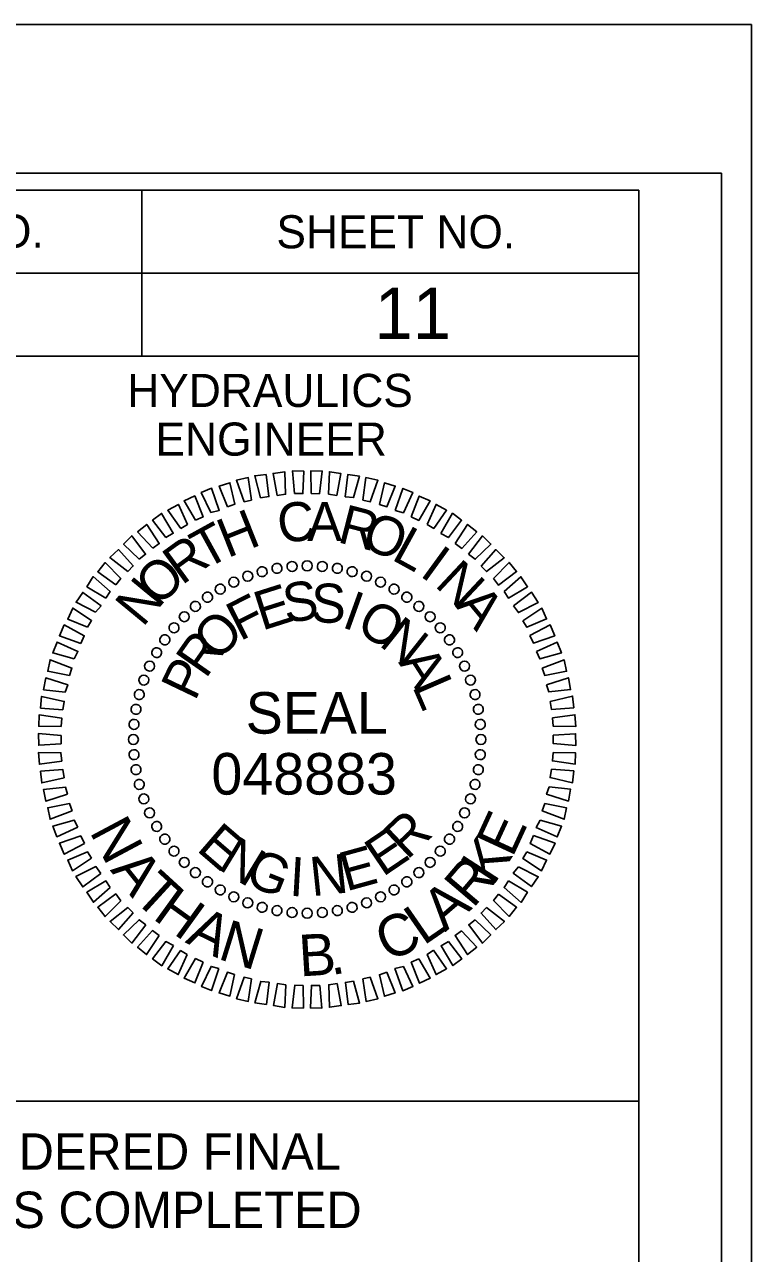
# Model space of a CAD drawing. Extents: x 1648157 to 1650776, y 832691 to 834781.
# Drawn here: x 1650436.6 to 1650546.3, y 833605.5 to 833791 of the extents above; entities that cross this region are included whole.
import ezdxf

# ---------------------------------------------------------------- set-up
doc = ezdxf.new("R2010")
doc.units = 0
for name, color, linetype in [('Default', 7, 'Continuous'), ('Old_Level_2', 7, 'Continuous'), ('Sheet Cutting Line CELL', 7, 'Continuous'), ('Sheet Data Field CELL', 7, 'Continuous'), ('Sheet Plot Border Inside CELL', 7, 'Continuous'), ('Sheet Plot Border Outside CELL', 7, 'Continuous'), ('Sheet Profile CELL', 7, 'Continuous'), ('Sheet Sticker Exception Certification CELL', 7, 'Continuous')]:
    doc.layers.add(name, color=color, linetype=linetype)

msp = doc.modelspace()

# ---------------------------------------------------------------- linework, layer by layer
at = {"layer": 'Old_Level_2'}
for p, q in [((1650474.7, 833708.89), (1650474.7, 833708.89)), ((1650476.94, 833709.25), (1650476.94, 833709.25)), ((1650479.24, 833709.34), (1650479.24, 833709.34)), ((1650481.55, 833709.22), (1650481.55, 833709.22)), ((1650483.8, 833708.9), (1650483.8, 833708.9)), ((1650468.15, 833706.9), (1650468.15, 833706.9)), ((1650470.22, 833707.77), (1650470.22, 833707.77)), ((1650472.41, 833708.44), (1650472.41, 833708.44)), ((1650486.01, 833708.46), (1650486.01, 833708.46)), ((1650488.21, 833707.77), (1650488.21, 833707.77)), ((1650490.32, 833706.87), (1650490.32, 833706.87)), ((1650466.13, 833705.82), (1650466.13, 833705.82)), ((1650492.38, 833705.86), (1650492.38, 833705.86)), ((1650462.35, 833703.24), (1650462.35, 833703.24)), ((1650464.16, 833704.58), (1650464.16, 833704.58)), ((1650494.28, 833704.58), (1650494.28, 833704.58)), ((1650496.14, 833703.2), (1650496.14, 833703.2)), ((1650460.66, 833701.64), (1650460.66, 833701.64)), ((1650497.79, 833701.66), (1650497.79, 833701.66)), ((1650459.12, 833699.99), (1650459.12, 833699.99)), ((1650499.38, 833699.96), (1650499.38, 833699.96)), ((1650457.74, 833698.14), (1650457.74, 833698.14)), ((1650500.72, 833698.16), (1650500.72, 833698.16)), ((1650456.46, 833696.23), (1650456.46, 833696.23)), ((1650501.96, 833696.19), (1650501.96, 833696.19)), ((1650455.45, 833694.18), (1650455.45, 833694.18)), ((1650503.04, 833694.17), (1650503.04, 833694.17)), ((1650454.55, 833692.07), (1650454.55, 833692.07)), ((1650503.91, 833692.09), (1650503.91, 833692.09)), ((1650453.85, 833689.86), (1650453.85, 833689.86)), ((1650504.58, 833689.91), (1650504.58, 833689.91)), ((1650453.42, 833687.66), (1650453.42, 833687.66)), ((1650505.04, 833687.62), (1650505.04, 833687.62)), ((1650453.1, 833685.4), (1650453.1, 833685.4)), ((1650505.39, 833685.37), (1650505.39, 833685.37)), ((1650452.98, 833683.1), (1650452.98, 833683.1)), ((1650479.23, 833683.09), (1650479.23, 833683.09)), ((1650505.48, 833683.07), (1650505.48, 833683.07)), ((1650453.07, 833680.8), (1650453.07, 833680.8)), ((1650505.37, 833680.77), (1650505.37, 833680.77)), ((1650453.42, 833678.56), (1650453.42, 833678.56)), ((1650505.04, 833678.52), (1650505.04, 833678.52)), ((1650453.88, 833676.26), (1650453.88, 833676.26)), ((1650504.61, 833676.31), (1650504.61, 833676.31)), ((1650454.55, 833674.08), (1650454.55, 833674.08)), ((1650503.92, 833674.1), (1650503.92, 833674.1)), ((1650455.42, 833672), (1650455.42, 833672)), ((1650503.01, 833672), (1650503.01, 833672)), ((1650456.5, 833669.98), (1650456.5, 833669.98)), ((1650502, 833669.94), (1650502, 833669.94)), ((1650457.74, 833668.02), (1650457.74, 833668.02)), ((1650500.73, 833668.03), (1650500.73, 833668.03)), ((1650459.08, 833666.21), (1650459.08, 833666.21)), ((1650499.35, 833666.18), (1650499.35, 833666.18)), ((1650460.68, 833664.51), (1650460.68, 833664.51)), ((1650497.81, 833664.53), (1650497.81, 833664.53)), ((1650462.32, 833662.97), (1650462.32, 833662.97)), ((1650496.11, 833662.93), (1650496.11, 833662.93)), ((1650464.18, 833661.59), (1650464.18, 833661.59)), ((1650466.08, 833660.32), (1650466.08, 833660.32)), ((1650492.34, 833660.36), (1650492.34, 833660.36)), ((1650494.3, 833661.59), (1650494.3, 833661.59)), ((1650468.14, 833659.31), (1650468.14, 833659.31)), ((1650490.32, 833659.28), (1650490.32, 833659.28)), ((1650470.25, 833658.4), (1650470.25, 833658.4)), ((1650472.46, 833657.71), (1650472.46, 833657.71)), ((1650474.66, 833657.28), (1650474.66, 833657.28)), ((1650476.92, 833656.95), (1650476.92, 833656.95)), ((1650479.22, 833656.83), (1650479.22, 833656.83)), ((1650481.52, 833656.93), (1650481.52, 833656.93)), ((1650483.76, 833657.28), (1650483.76, 833657.28)), ((1650486.05, 833657.74), (1650486.05, 833657.74)), ((1650488.24, 833658.4), (1650488.24, 833658.4))]:
    msp.add_line(p, q, dxfattribs=at)
for points in [[(1650474.72, 833719.93), (1650474.08, 833723.26), (1650475.86, 833723.5), (1650475.97, 833720.11)], [(1650477.33, 833720.24), (1650477.01, 833723.63), (1650478.73, 833723.61), (1650478.58, 833720.21)], [(1650479.84, 833720.23), (1650479.78, 833723.63), (1650481.5, 833723.6), (1650481.09, 833720.2)], [(1650482.45, 833720.12), (1650482.6, 833723.52), (1650484.34, 833723.23), (1650483.71, 833719.93)], [(1650467.22, 833718.23), (1650465.96, 833721.34), (1650467.57, 833721.84), (1650468.31, 833718.61)], [(1650469.71, 833718.95), (1650468.56, 833722.23), (1650470.33, 833722.62), (1650470.81, 833719.23)], [(1650472.21, 833719.57), (1650471.32, 833722.9), (1650473.04, 833723.09), (1650473.47, 833719.75)], [(1650484.97, 833719.74), (1650485.38, 833723.1), (1650487.11, 833722.86), (1650486.23, 833719.61)], [(1650487.65, 833719.21), (1650488.11, 833722.62), (1650489.9, 833722.23), (1650488.75, 833718.97)], [(1650490.17, 833718.58), (1650490.9, 833721.83), (1650492.53, 833721.34), (1650491.27, 833718.23)], [(1650462.39, 833716.21), (1650460.66, 833719.11), (1650462.27, 833719.87), (1650463.53, 833716.7)], [(1650464.67, 833717.35), (1650463.26, 833720.36), (1650464.82, 833721.01), (1650465.97, 833717.68)], [(1650492.54, 833717.68), (1650493.68, 833720.99), (1650495.16, 833720.39), (1650493.75, 833717.33)], [(1650494.91, 833716.72), (1650496.16, 833719.83), (1650497.79, 833719.13), (1650496.07, 833716.17)], [(1650460.16, 833714.92), (1650458.18, 833717.71), (1650459.79, 833718.57), (1650461.15, 833715.56)], [(1650497.33, 833715.56), (1650498.69, 833718.57), (1650500.28, 833717.71), (1650498.34, 833714.95)], [(1650457.89, 833713.57), (1650455.9, 833716.2), (1650457.25, 833717.22), (1650459.02, 833714.22)], [(1650499.4, 833714.19), (1650501.17, 833717.25), (1650502.55, 833716.18), (1650500.56, 833713.58)], [(1650455.93, 833711.97), (1650453.63, 833714.44), (1650455.03, 833715.56), (1650456.91, 833712.66)], [(1650501.57, 833712.66), (1650503.45, 833715.57), (1650504.83, 833714.44), (1650502.57, 833711.94)], [(1650453.86, 833710.31), (1650451.52, 833712.57), (1650452.76, 833713.85), (1650454.84, 833711.06)], [(1650503.58, 833711.07), (1650505.68, 833713.83), (1650506.96, 833712.59), (1650504.59, 833710.3)], [(1650452.17, 833708.45), (1650449.47, 833710.55), (1650450.75, 833711.77), (1650452.99, 833709.3)], [(1650505.5, 833709.27), (1650507.7, 833711.77), (1650508.98, 833710.54), (1650506.3, 833708.45)], [(1650450.37, 833706.43), (1650447.62, 833708.42), (1650448.75, 833709.8), (1650451.09, 833707.38)], [(1650507.36, 833707.42), (1650509.72, 833709.82), (1650510.85, 833708.43), (1650508.11, 833706.39)], [(1650448.84, 833704.42), (1650445.99, 833706.14), (1650446.95, 833707.68), (1650449.5, 833705.42)], [(1650508.96, 833705.41), (1650511.49, 833707.65), (1650512.51, 833706.15), (1650509.61, 833704.43)], [(1650447.31, 833702.3), (1650444.35, 833703.81), (1650445.37, 833705.3), (1650448.13, 833703.25)], [(1650510.36, 833703.29), (1650513.1, 833705.33), (1650514.12, 833703.78), (1650511.11, 833702.26)], [(1650446.09, 833700.03), (1650443.09, 833701.28), (1650443.85, 833702.92), (1650446.7, 833701.03)], [(1650511.76, 833701.02), (1650514.66, 833702.9), (1650515.36, 833701.29), (1650512.41, 833700.03)], [(1650445.09, 833697.6), (1650441.83, 833698.75), (1650442.58, 833700.38), (1650445.59, 833698.76)], [(1650512.85, 833698.79), (1650515.9, 833700.41), (1650516.61, 833698.75), (1650513.39, 833697.65)], [(1650444.08, 833695.29), (1650440.83, 833696.17), (1650441.48, 833697.8), (1650444.64, 833696.39)], [(1650513.83, 833696.35), (1650516.99, 833697.76), (1650517.6, 833696.15), (1650514.37, 833695.26)], [(1650443.34, 833692.76), (1650440.09, 833693.39), (1650440.43, 833695.12), (1650443.74, 833693.87)], [(1650514.71, 833693.85), (1650518.03, 833695.11), (1650518.38, 833693.39), (1650515.09, 833692.76)], [(1650442.71, 833690.24), (1650439.46, 833690.6), (1650439.79, 833692.39), (1650443.11, 833691.35)], [(1650515.38, 833691.35), (1650518.66, 833692.4), (1650519, 833690.63), (1650515.71, 833690.26)], [(1650442.34, 833687.57), (1650438.99, 833687.82), (1650439.16, 833689.6), (1650442.58, 833688.83)], [(1650515.89, 833688.85), (1650519.28, 833689.64), (1650519.47, 833687.87), (1650516.13, 833687.6)], [(1650442.12, 833685.05), (1650438.72, 833685.1), (1650438.79, 833686.83), (1650442.2, 833686.31)], [(1650516.25, 833686.35), (1650519.64, 833686.82), (1650519.78, 833685.05), (1650516.38, 833685.09)], [(1650442.11, 833682.44), (1650438.72, 833682.22), (1650438.69, 833684), (1650442.09, 833683.69)], [(1650516.35, 833683.73), (1650519.75, 833683.95), (1650519.78, 833682.17), (1650516.37, 833682.48)], [(1650442.21, 833679.83), (1650438.82, 833679.35), (1650438.68, 833681.12), (1650442.08, 833681.08)], [(1650516.34, 833681.12), (1650519.74, 833681.07), (1650519.67, 833679.35), (1650516.26, 833679.86)], [(1650442.57, 833677.32), (1650439.18, 833676.53), (1650438.99, 833678.3), (1650442.34, 833678.57)], [(1650516.13, 833678.61), (1650519.48, 833678.35), (1650519.3, 833676.57), (1650515.89, 833677.35)], [(1650443.08, 833674.82), (1650439.81, 833673.77), (1650439.46, 833675.54), (1650442.75, 833675.91)], [(1650515.75, 833675.93), (1650519, 833675.57), (1650518.67, 833673.79), (1650515.36, 833674.83)], [(1650443.75, 833672.32), (1650440.43, 833671.06), (1650440.08, 833672.78), (1650443.37, 833673.41)], [(1650515.12, 833673.41), (1650518.37, 833672.79), (1650518.04, 833671.06), (1650514.72, 833672.31)], [(1650444.63, 833669.83), (1650441.47, 833668.41), (1650440.86, 833670.02), (1650444.09, 833670.92)], [(1650514.38, 833670.89), (1650517.64, 833670), (1650516.98, 833668.37), (1650513.82, 833669.78)], [(1650445.62, 833667.39), (1650442.56, 833665.76), (1650441.85, 833667.42), (1650445.07, 833668.53)], [(1650513.37, 833668.57), (1650516.64, 833667.42), (1650515.88, 833665.79), (1650512.87, 833667.41)], [(1650446.7, 833665.16), (1650443.81, 833663.28), (1650443.1, 833664.88), (1650446.06, 833666.14)], [(1650512.37, 833666.15), (1650515.37, 833664.89), (1650514.62, 833663.26), (1650511.76, 833665.14)], [(1650448.1, 833662.88), (1650445.37, 833660.84), (1650444.34, 833662.4), (1650447.35, 833663.91)], [(1650511.15, 833663.88), (1650514.11, 833662.36), (1650513.09, 833660.88), (1650510.33, 833662.92)], [(1650449.5, 833660.76), (1650446.97, 833658.52), (1650445.96, 833660.02), (1650448.85, 833661.74)], [(1650509.62, 833661.76), (1650512.48, 833660.03), (1650511.51, 833658.5), (1650508.96, 833660.75)], [(1650451.1, 833658.75), (1650448.74, 833656.35), (1650447.62, 833657.75), (1650450.35, 833659.78)], [(1650508.09, 833659.74), (1650510.84, 833657.75), (1650509.72, 833656.37), (1650507.37, 833658.79)], [(1650452.97, 833656.9), (1650450.76, 833654.4), (1650449.48, 833655.63), (1650452.17, 833657.72)], [(1650506.29, 833657.72), (1650509, 833655.63), (1650507.71, 833654.4), (1650505.47, 833656.87)], [(1650454.88, 833655.1), (1650452.78, 833652.35), (1650451.51, 833653.58), (1650453.87, 833655.87)], [(1650504.6, 833655.86), (1650506.94, 833653.6), (1650505.71, 833652.33), (1650503.62, 833655.12)], [(1650456.89, 833653.52), (1650455.01, 833650.61), (1650453.63, 833651.73), (1650455.89, 833654.23)], [(1650502.54, 833654.21), (1650504.83, 833651.74), (1650503.44, 833650.61), (1650501.56, 833653.51)], [(1650459.06, 833651.98), (1650457.29, 833648.92), (1650455.91, 833649.99), (1650457.9, 833652.59)], [(1650461.13, 833650.61), (1650459.77, 833647.6), (1650458.18, 833648.46), (1650460.12, 833651.22)], [(1650498.3, 833651.26), (1650500.28, 833648.47), (1650498.68, 833647.6), (1650497.32, 833650.61)], [(1650500.58, 833652.6), (1650502.56, 833649.97), (1650501.22, 833648.95), (1650499.44, 833651.96)], [(1650463.55, 833649.45), (1650462.3, 833646.34), (1650460.67, 833647.04), (1650462.39, 833650)], [(1650496.07, 833649.96), (1650497.8, 833647.06), (1650496.19, 833646.3), (1650494.93, 833649.47)], [(1650465.92, 833648.5), (1650464.78, 833645.18), (1650463.3, 833645.78), (1650464.72, 833648.84)], [(1650468.29, 833647.6), (1650467.57, 833644.34), (1650465.94, 833644.83), (1650467.19, 833647.94)], [(1650491.25, 833647.94), (1650492.5, 833644.83), (1650490.89, 833644.33), (1650490.15, 833647.56)], [(1650493.79, 833648.82), (1650495.2, 833645.82), (1650493.65, 833645.16), (1650492.49, 833648.49)], [(1650470.81, 833646.96), (1650470.35, 833643.55), (1650468.57, 833643.94), (1650469.71, 833647.2)], [(1650473.49, 833646.43), (1650473.08, 833643.08), (1650471.35, 833643.31), (1650472.23, 833646.57)], [(1650476.01, 833646.06), (1650475.86, 833642.65), (1650474.13, 833642.94), (1650474.75, 833646.24)], [(1650478.62, 833645.95), (1650478.68, 833642.55), (1650476.96, 833642.57), (1650477.37, 833645.98)], [(1650481.13, 833645.94), (1650481.46, 833642.54), (1650479.73, 833642.57), (1650479.88, 833645.97)], [(1650483.74, 833646.24), (1650484.38, 833642.91), (1650482.6, 833642.67), (1650482.49, 833646.07)], [(1650486.25, 833646.6), (1650487.14, 833643.27), (1650485.42, 833643.08), (1650485, 833646.42)], [(1650488.75, 833647.22), (1650489.9, 833643.95), (1650488.13, 833643.55), (1650487.65, 833646.94)]]:
    msp.add_lwpolyline(points, close=True, dxfattribs=at)
for centre, major_axis in [((1650470.26, 833707.73), (-0.258, 0.708)), ((1650472.44, 833708.42), (-0.195, 0.727)), ((1650474.68, 833708.92), (-0.131, 0.742)), ((1650476.95, 833709.21), (-0.066, 0.75)), ((1650479.23, 833709.31), (0, 0.753)), ((1650481.52, 833709.21), (0.066, 0.75)), ((1650483.79, 833708.92), (0.131, 0.742)), ((1650486.02, 833708.42), (0.195, 0.727)), ((1650488.2, 833707.73), (0.258, 0.708)), ((1650468.15, 833706.86), (-0.318, 0.682)), ((1650490.32, 833706.86), (0.318, 0.682)), ((1650464.19, 833704.57), (-0.432, 0.617)), ((1650466.12, 833705.8), (-0.376, 0.652)), ((1650492.35, 833705.8), (0.376, 0.652)), ((1650494.27, 833704.57), (0.432, 0.617)), ((1650462.37, 833703.18), (-0.484, 0.577)), ((1650496.09, 833703.18), (0.484, 0.577)), ((1650460.69, 833701.63), (-0.532, 0.532)), ((1650497.78, 833701.63), (0.532, 0.532)), ((1650459.14, 833699.95), (-0.577, 0.484)), ((1650499.32, 833699.95), (0.577, 0.484)), ((1650457.75, 833698.13), (-0.617, 0.432)), ((1650500.72, 833698.13), (0.617, 0.432)), ((1650456.52, 833696.2), (-0.652, 0.376)), ((1650501.95, 833696.2), (0.652, 0.376)), ((1650455.46, 833694.17), (-0.682, 0.318)), ((1650503, 833694.17), (0.682, 0.318)), ((1650454.59, 833692.06), (-0.708, 0.258)), ((1650503.88, 833692.06), (0.708, 0.258)), ((1650453.9, 833689.87), (-0.727, 0.195)), ((1650504.57, 833689.87), (0.727, 0.195)), ((1650453.4, 833687.64), (-0.742, 0.131)), ((1650505.06, 833687.64), (0.742, 0.131)), ((1650453.1, 833685.37), (-0.75, 0.066)), ((1650505.36, 833685.37), (0.75, 0.066)), ((1650453, 833683.09), (-0.753, 0)), ((1650505.46, 833683.09), (0.753, 0)), ((1650453.1, 833680.8), (-0.75, -0.066)), ((1650505.36, 833680.8), (0.75, -0.066)), ((1650453.4, 833678.53), (-0.742, -0.131)), ((1650505.06, 833678.53), (0.742, -0.131)), ((1650453.9, 833676.3), (-0.727, -0.195)), ((1650504.57, 833676.3), (0.727, -0.195)), ((1650454.59, 833674.12), (-0.708, -0.258)), ((1650503.88, 833674.12), (0.708, -0.258)), ((1650455.46, 833672), (-0.682, -0.318)), ((1650503, 833672), (0.682, -0.318)), ((1650456.52, 833669.97), (-0.652, -0.376)), ((1650501.95, 833669.97), (0.652, -0.376)), ((1650457.75, 833668.04), (-0.617, -0.432)), ((1650500.72, 833668.04), (0.617, -0.432)), ((1650459.14, 833666.23), (-0.577, -0.484)), ((1650499.32, 833666.23), (0.577, -0.484)), ((1650460.69, 833664.54), (-0.532, -0.532)), ((1650497.78, 833664.54), (0.532, -0.532)), ((1650462.37, 833662.99), (-0.484, -0.577)), ((1650464.19, 833661.6), (-0.432, -0.617)), ((1650494.27, 833661.6), (0.432, -0.617)), ((1650496.09, 833662.99), (0.484, -0.577)), ((1650466.12, 833660.37), (-0.376, -0.652)), ((1650492.35, 833660.37), (0.376, -0.652)), ((1650468.15, 833659.32), (-0.318, -0.682)), ((1650470.26, 833658.44), (-0.258, -0.708)), ((1650472.44, 833657.75), (-0.195, -0.727)), ((1650486.02, 833657.75), (0.195, -0.727)), ((1650488.2, 833658.44), (0.258, -0.708)), ((1650490.32, 833659.32), (0.318, -0.682)), ((1650474.68, 833657.26), (-0.131, -0.742)), ((1650476.95, 833656.96), (-0.066, -0.75)), ((1650479.23, 833656.86), (0, -0.753)), ((1650481.52, 833656.96), (0.066, -0.75)), ((1650483.79, 833657.26), (0.131, -0.742))]:
    msp.add_ellipse(centre, major_axis=major_axis, ratio=0.999708, dxfattribs=at)
at = {"layer": 'Sheet Cutting Line CELL'}
msp.add_line((1650546.28, 833791.02), (1648862.28, 833791.02), dxfattribs=at)
at = {"layer": 'Sheet Plot Border Inside CELL'}
msp.add_lwpolyline([(1648875.28, 832713.47), (1650541.78, 832713.47), (1650541.78, 833768.57), (1648875.28, 833768.57)], close=True, dxfattribs=at)
at = {"layer": 'Sheet Plot Border Outside CELL'}
msp.add_lwpolyline([(1648862.28, 832691.02), (1650546.28, 832691.02), (1650546.28, 833791.02), (1648862.28, 833791.02)], close=True, dxfattribs=at)
at = {"layer": 'Sheet Profile CELL'}
for p, q in [((1650454.28, 833765.97), (1650454.28, 833740.97)), ((1650329.23, 833753.47), (1650529.28, 833753.47))]:
    msp.add_line(p, q, dxfattribs=at)
for points in [[(1650529.28, 833766.02), (1649029.28, 833766.02), (1649029.28, 832716.02), (1650529.28, 832716.02)], [(1650329.23, 833766.02), (1650529.28, 833766.02), (1650529.28, 833740.97), (1650329.23, 833740.97)], [(1650429.28, 833740.97), (1650529.28, 833740.97), (1650529.28, 833628.47), (1650429.28, 833628.47)]]:
    msp.add_lwpolyline(points, close=True, dxfattribs=at)
at = {"layer": 'Sheet Sticker Exception Certification CELL'}
for p, q in [((1650329.23, 833628.47), (1650529.27, 833628.47)), ((1650329.23, 833628.47), (1650529.27, 833628.47)), ((1650529.27, 833628.46), (1650529.27, 833604.96)), ((1650529.27, 833628.46), (1650529.27, 833604.96))]:
    msp.add_line(p, q, dxfattribs=at)

# ---------------------------------------------------------------- texts
at = {"layer": 'Default'}
for s, rotation, p in [('N', 298.0773, (1650446.31, 833669.19)), ('E', 65.2198, (1650510.2, 833665.13)), ('K', 57.024, (1650507.33, 833660.9)), ('A', 308.6891, (1650449.42, 833663.36)), ('R', 49.6233, (1650504.25, 833657.47)), ('T', 317.4354, (1650452.76, 833659.05)), ('H', 324.1633, (1650455.75, 833656.11)), ('A', 40.877, (1650500.07, 833653.97)), ('A', 334.0411, (1650460.72, 833652.48)), ('C', 25.1886, (1650491.43, 833649.42)), ('L', 34.6689, (1650496.8, 833651.89)), ('N', 342.7874, (1650465.58, 833650.01)), ('B', 3.4911, (1650478.14, 833647.31)), ('.', 11.1059, (1650482.89, 833647.47))]:
    msp.add_text(s, height=6.27, rotation=rotation, dxfattribs=at).set_placement(p)
at = {"layer": 'Old_Level_2'}
for s, rotation, p in [('C', 7.2199, (1650475.11, 833712.67)), ('A', 0.0203, (1650479.23, 833713.05)), ('R', 345.6211, (1650483.63, 833712.92)), ('T', 28.8198, (1650463.83, 833708.65)), ('H', 21.6195, (1650467.2, 833710.44)), ('O', 338.4212, (1650487.14, 833712.2)), ('L', 331.2209, (1650491.78, 833710.34)), ('R', 36.0205, (1650460.31, 833706.29)), ('I', 324.0201, (1650496.06, 833707.91)), ('O', 43.2217, (1650456.76, 833702.99)), ('N', 316.8189, (1650498.33, 833706.33)), ('N', 50.4235, (1650454.41, 833699.91)), ('S', 8.2556, (1650476, 833700.65)), ('S', 358.9004, (1650479.76, 833700.77)), ('F', 26.967, (1650469.09, 833697.87)), ('E', 17.6111, (1650472.41, 833699.49)), ('I', 340.1896, (1650484.27, 833700.12)), ('A', 309.6172, (1650501.47, 833703.29)), ('O', 330.8335, (1650486.37, 833699.42)), ('O', 45.6812, (1650465.69, 833694.72)), ('N', 321.4766, (1650489.91, 833697.39)), ('R', 55.0397, (1650463.91, 833692.13)), ('A', 302.7603, (1650492.94, 833694.73)), ('P', 64.3989, (1650462.29, 833688.75)), ('L', 293.4009, (1650495.04, 833691.15)), ('R', 43.4814, (1650494.3, 833664.78)), ('E', 319.2769, (1650462.37, 833666.42)), ('E', 34.1241, (1650490.63, 833662.26)), ('N', 328.634, (1650465.56, 833663.65)), ('G', 337.9902, (1650469.57, 833661.37)), ('E', 15.4118, (1650485.12, 833660.13)), ('I', 356.7012, (1650476.45, 833659.5)), ('N', 6.0564, (1650479.96, 833659.41))]:
    msp.add_text(s, height=5.9, rotation=rotation, dxfattribs=at).set_placement(p)
for s, height, p in [('SEAL', 6.273, (1650469.96, 833683.97)), ('048883', 6.275, (1650464.78, 833674.77))]:
    msp.add_text(s, height=height, dxfattribs=at).set_placement(p)
at = {"layer": 'Sheet Data Field CELL'}
msp.add_text('11', height=7.75, dxfattribs=at).set_placement((1650489.41, 833743.57))
at = {"layer": 'Sheet Profile CELL'}
for s, height, p in [('PROJECT REFERENCE NO.', 5.0001, (1650351.44, 833757.34)), ('SHEET NO.', 5, (1650474.59, 833757.24)), ('HYDRAULICS', 5, (1650452.09, 833733.29)), ('ENGINEER', 5, (1650456.34, 833725.94))]:
    msp.add_text(s, height=height, dxfattribs=at).set_placement(p)
at = {"layer": 'Sheet Sticker Exception Certification CELL'}
for s, p in [('DOCUMENT NOT CONSIDERED FINAL', (1650350.3, 833618.13)), ('DOCUMENT NOT CONSIDERED FINAL', (1650350.3, 833618.13)), ('UNLESS ALL SIGNATURES COMPLETED', (1650345.23, 833609.33)), ('UNLESS ALL SIGNATURES COMPLETED', (1650345.23, 833609.33))]:
    msp.add_text(s, height=5.5, dxfattribs=at).set_placement(p)

doc.saveas('drawing.dxf')
